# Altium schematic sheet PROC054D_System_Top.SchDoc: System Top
size 558 x 431 mm; Date: Not shown in title block; ApprovedBy: Not shown in title block; CheckedBy: Not shown in title block; Author: Not shown in title block; CompanyName: Not shown in title block; DrawnBy: a0271760; Engineer: Not shown in title block; Organization: Not shown in title block; Address1: Not shown in title block; Address2: Not shown in title block; Address3: Not shown in title block; Address4: Not shown in title block; DocumentNumber: 2; Revision: Use project parameter SCH_Rev; SheetNumber: 2; SheetTotal: 19; PageSetup: Record=PageOptions¦CenterHorizontal=True¦CenterVertical=True¦PrintScale=1.00¦XCorrection=1.00¦YCorrection=1.00¦PrintKind=0¦BorderSize=5000000¦LeftOffset=0¦BottomOffset=0¦Orientation=2¦PaperLength=1000¦PaperWidth=1000¦Scale=100¦PaperSource=15¦PrintQuality=600¦MediaType=1¦DitherType=10¦PaperKind=Letter¦PrintScaleMode=1
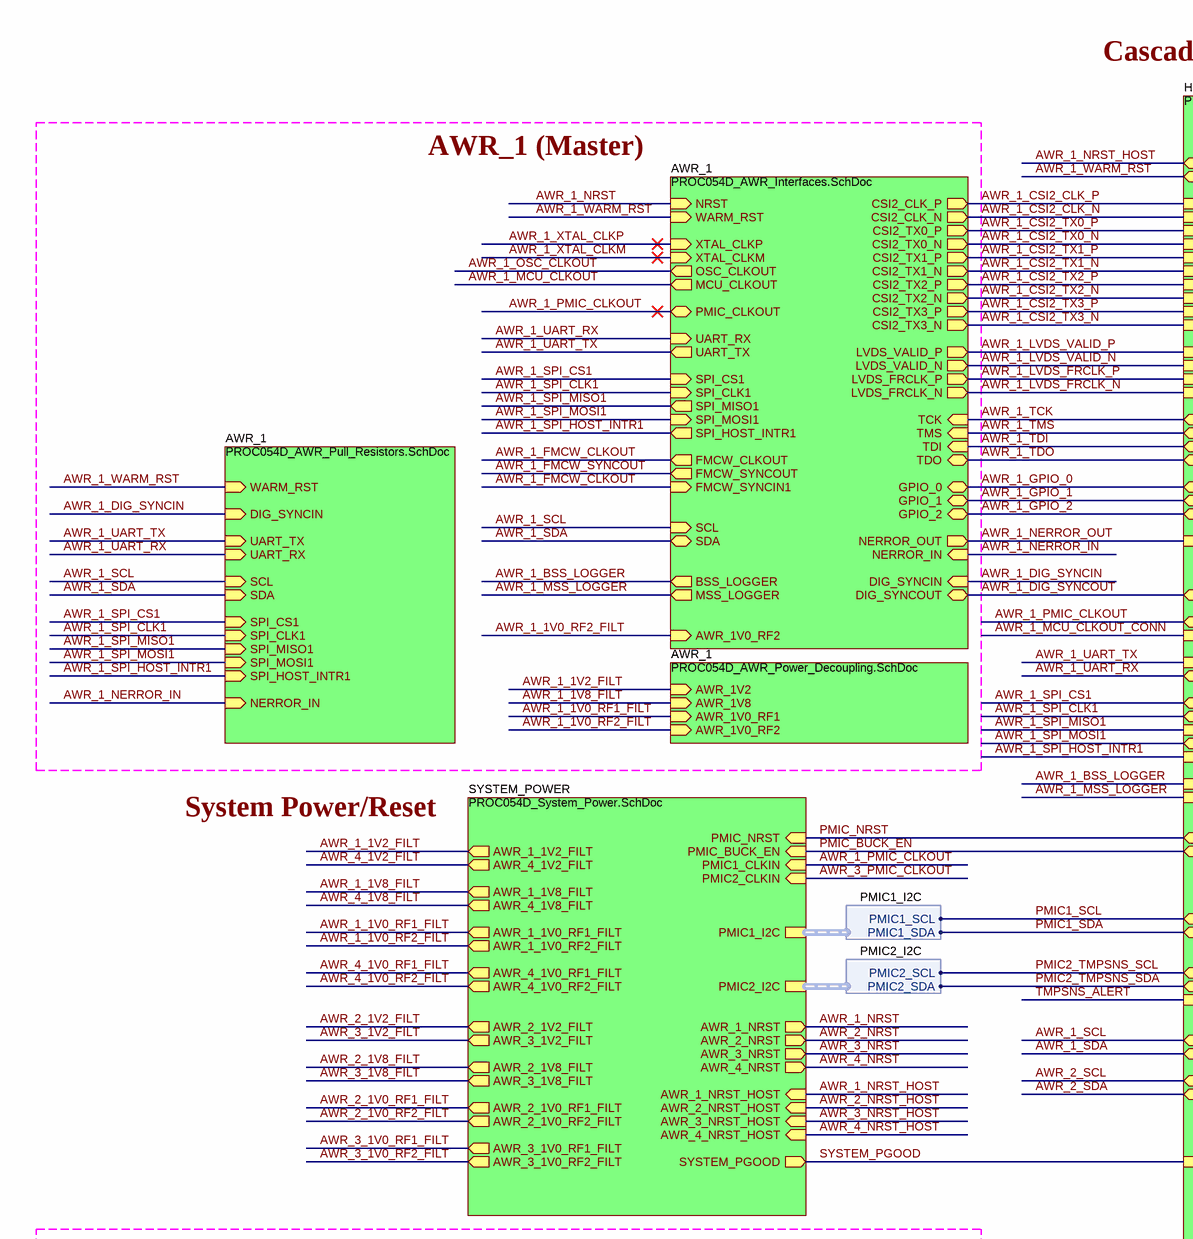
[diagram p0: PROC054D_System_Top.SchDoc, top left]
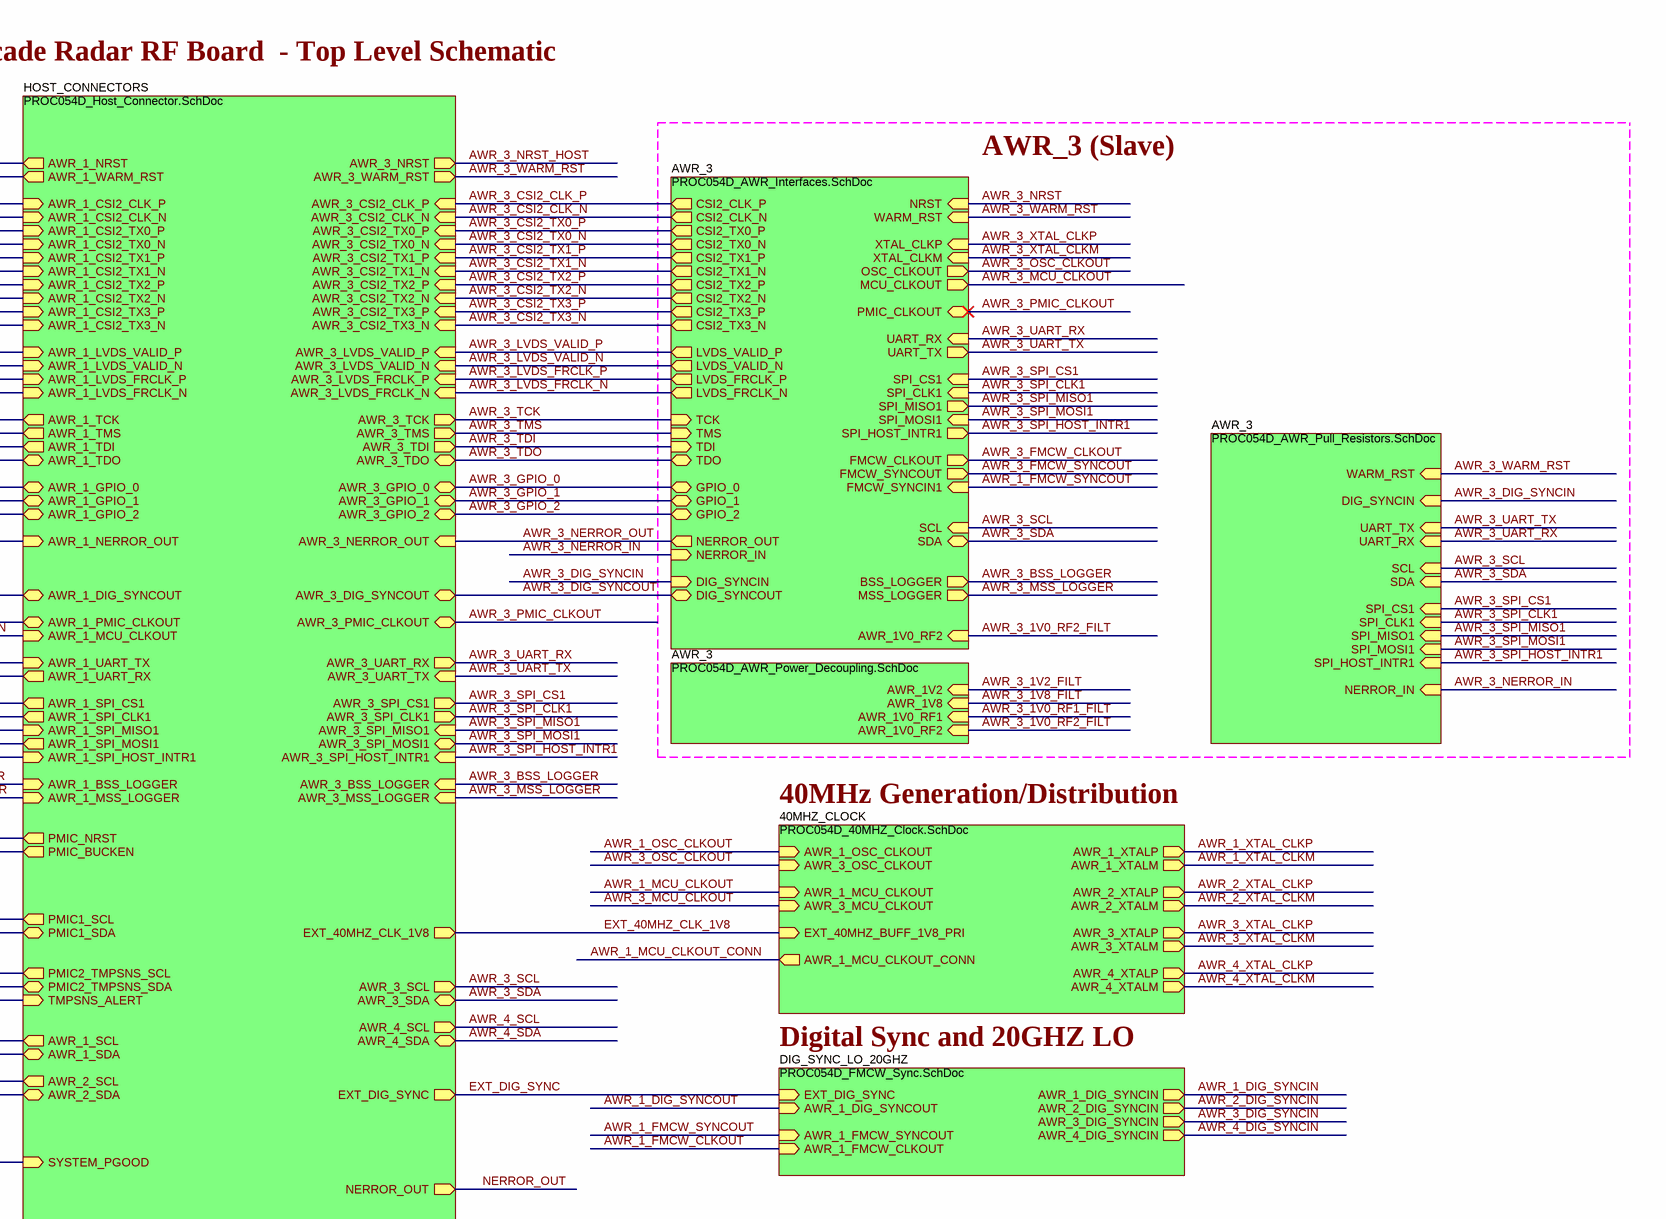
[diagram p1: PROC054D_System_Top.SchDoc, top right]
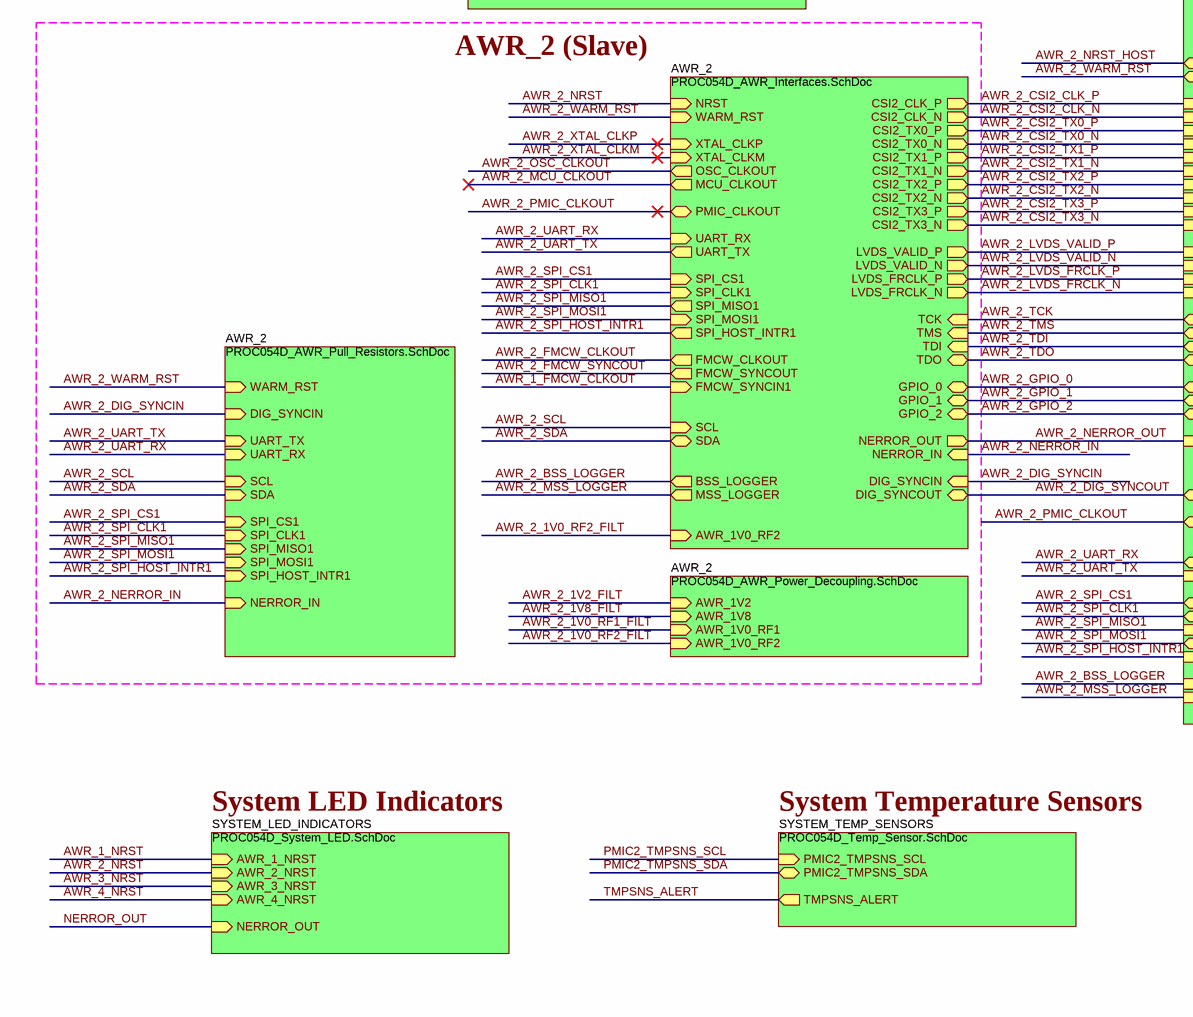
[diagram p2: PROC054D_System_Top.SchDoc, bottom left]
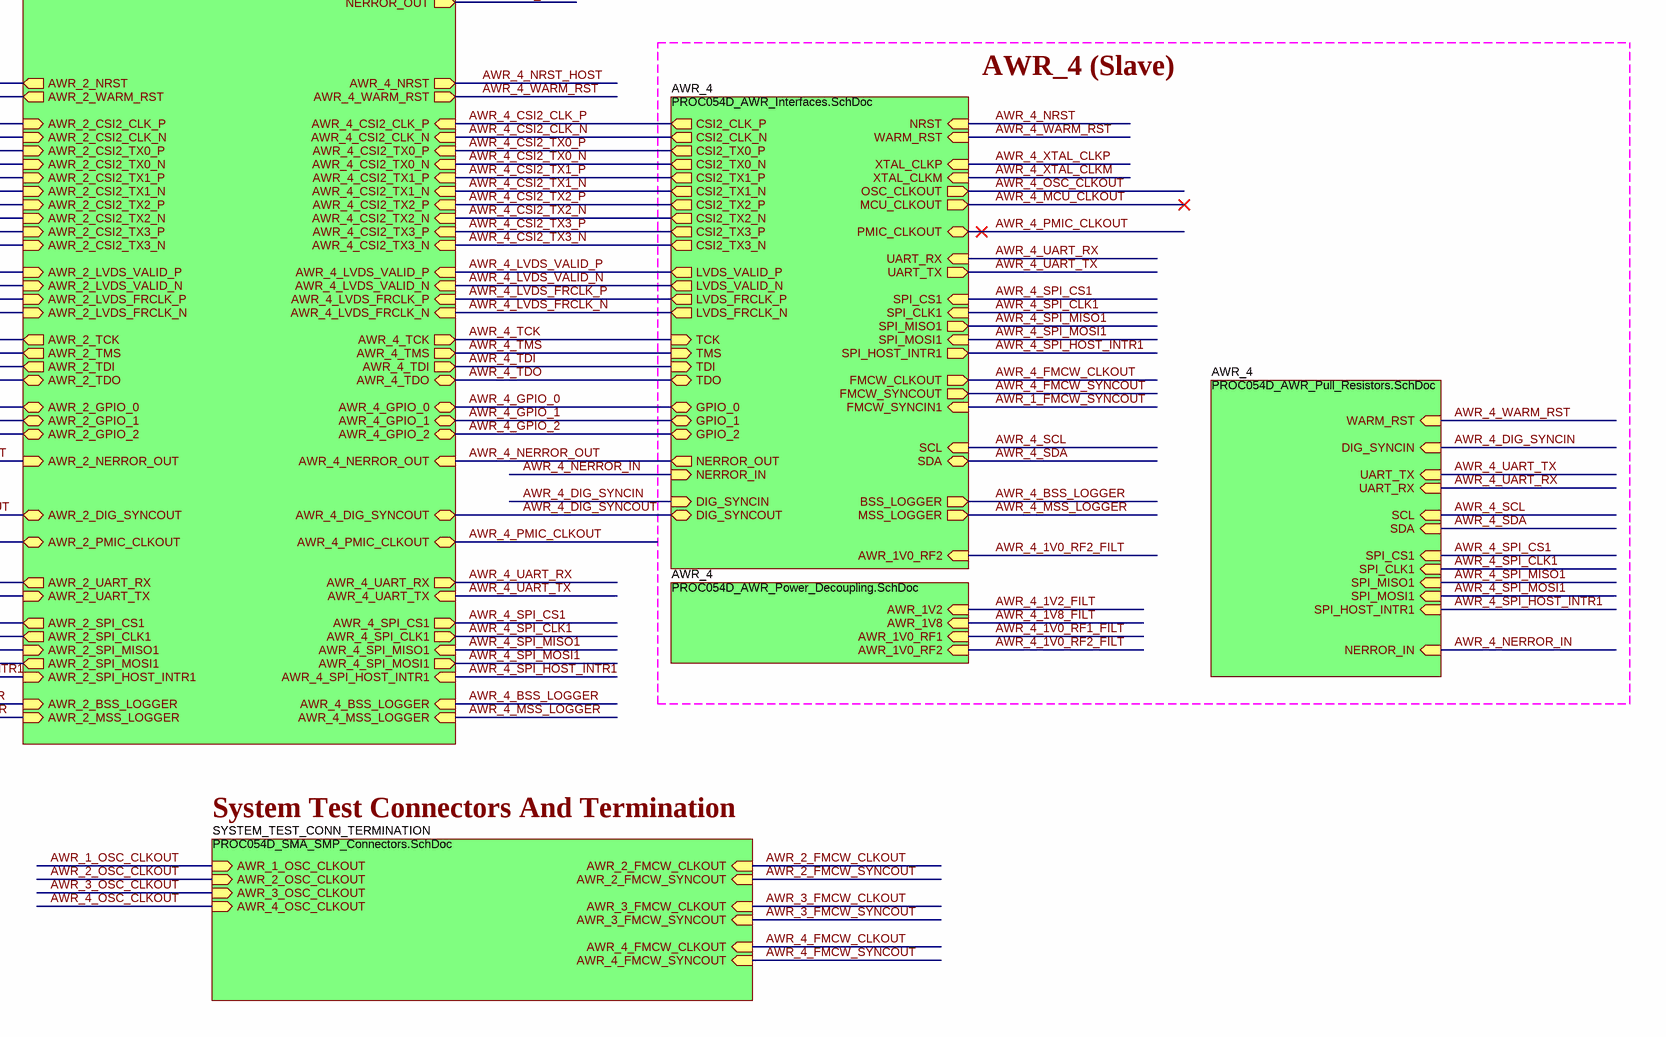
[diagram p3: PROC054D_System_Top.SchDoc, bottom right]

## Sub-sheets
40MHZ_CLOCK = PROC054D_40MHZ_Clock.SchDoc: AWR_4_XTALP (out), AWR_2_XTALP (out), AWR_3_XTALM (out), AWR_3_XTALP (out), AWR_4_XTALM (out), AWR_2_XTALM (out), AWR_1_XTALM (out), AWR_1_XTALP (out), EXT_40MHZ_BUFF_1V8_PRI (in), AWR_3_OSC_CLKOUT (in), AWR_1_MCU_CLKOUT (in), AWR_3_MCU_CLKOUT (in), AWR_1_OSC_CLKOUT (in), AWR_1_MCU_CLKOUT_CONN (out)
AWR_1 = PROC054D_AWR_Interfaces.SchDoc: OSC_CLKOUT (out), PMIC_CLKOUT (bidir), XTAL_CLKP (in), CSI2_TX2_P (out), CSI2_TX2_N (out), CSI2_TX3_P (out), CSI2_TX3_N (out), LVDS_FRCLK_P (out), LVDS_FRCLK_N (out), NERROR_OUT (out), NERROR_IN (in), XTAL_CLKM (in), LVDS_VALID_N (out), WARM_RST (in), NRST (in), CSI2_CLK_P (out), CSI2_CLK_N (out), TCK (in), CSI2_TX1_N (out), TDO (bidir), TMS (in), TDI (in), LVDS_VALID_P (out), CSI2_TX0_N (out), CSI2_TX1_P (out), CSI2_TX0_P (out), MCU_CLKOUT (out), DIG_SYNCOUT (bidir), DIG_SYNCIN (in), GPIO_0 (bidir), GPIO_1 (bidir), GPIO_2 (bidir), UART_RX (in), UART_TX (out), SPI_CLK1 (in), SPI_HOST_INTR1 (out), SPI_CS1 (in), SPI_MOSI1 (in), SPI_MISO1 (out), FMCW_SYNCIN1 (in), FMCW_CLKOUT (out), FMCW_SYNCOUT (out), SCL (in), SDA (bidir), BSS_LOGGER (out), MSS_LOGGER (out), AWR_1V0_RF2 (in)
AWR_1 = PROC054D_AWR_Power_Decoupling.SchDoc: AWR_1V0_RF1 (in), AWR_1V8 (in), AWR_1V2 (in), AWR_1V0_RF2 (in)
AWR_1 = PROC054D_AWR_Pull_Resistors.SchDoc: DIG_SYNCIN (in), SPI_CS1 (in), WARM_RST (in), UART_TX (in), UART_RX (in), SCL (in), SDA (in), SPI_CLK1 (in), SPI_MOSI1 (in), SPI_MISO1 (in), SPI_HOST_INTR1 (in), NERROR_IN (in)
AWR_2 = PROC054D_AWR_Interfaces.SchDoc: OSC_CLKOUT (out), PMIC_CLKOUT (bidir), XTAL_CLKP (in), CSI2_TX2_P (out), CSI2_TX2_N (out), CSI2_TX3_P (out), CSI2_TX3_N (out), LVDS_FRCLK_P (out), LVDS_FRCLK_N (out), NERROR_OUT (out), NERROR_IN (in), XTAL_CLKM (in), LVDS_VALID_N (out), WARM_RST (in), NRST (in), CSI2_CLK_P (out), CSI2_CLK_N (out), TCK (in), CSI2_TX1_N (out), TDO (bidir), TMS (in), TDI (in), LVDS_VALID_P (out), CSI2_TX0_N (out), CSI2_TX1_P (out), CSI2_TX0_P (out), MCU_CLKOUT (out), DIG_SYNCOUT (bidir), DIG_SYNCIN (in), GPIO_0 (bidir), GPIO_1 (bidir), GPIO_2 (bidir), UART_RX (in), UART_TX (out), SPI_CLK1 (in), SPI_HOST_INTR1 (out), SPI_CS1 (in), SPI_MOSI1 (in), SPI_MISO1 (out), FMCW_SYNCIN1 (in), FMCW_CLKOUT (out), FMCW_SYNCOUT (out), SCL (in), SDA (bidir), BSS_LOGGER (out), MSS_LOGGER (out), AWR_1V0_RF2 (in)
AWR_2 = PROC054D_AWR_Power_Decoupling.SchDoc: AWR_1V0_RF1 (in), AWR_1V8 (in), AWR_1V2 (in), AWR_1V0_RF2 (in)
AWR_2 = PROC054D_AWR_Pull_Resistors.SchDoc: DIG_SYNCIN (in), SPI_CS1 (in), WARM_RST (in), UART_TX (in), UART_RX (in), SCL (in), SDA (in), SPI_CLK1 (in), SPI_MOSI1 (in), SPI_MISO1 (in), SPI_HOST_INTR1 (in), NERROR_IN (in)
AWR_3 = PROC054D_AWR_Power_Decoupling.SchDoc: AWR_1V0_RF1 (in), AWR_1V8 (in), AWR_1V2 (in), AWR_1V0_RF2 (in)
AWR_3 = PROC054D_AWR_Pull_Resistors.SchDoc: DIG_SYNCIN (in), SPI_CS1 (in), WARM_RST (in), UART_TX (in), UART_RX (in), SCL (in), SDA (in), SPI_CLK1 (in), SPI_MOSI1 (in), SPI_MISO1 (in), SPI_HOST_INTR1 (in), NERROR_IN (in)
AWR_3 = PROC054D_AWR_Interfaces.SchDoc: OSC_CLKOUT (out), PMIC_CLKOUT (bidir), XTAL_CLKP (in), CSI2_TX2_P (out), CSI2_TX2_N (out), CSI2_TX3_P (out), CSI2_TX3_N (out), LVDS_FRCLK_P (out), LVDS_FRCLK_N (out), NERROR_OUT (out), NERROR_IN (in), XTAL_CLKM (in), LVDS_VALID_N (out), WARM_RST (in), NRST (in), CSI2_CLK_P (out), CSI2_CLK_N (out), TCK (in), CSI2_TX1_N (out), TDO (bidir), TMS (in), TDI (in), LVDS_VALID_P (out), CSI2_TX0_N (out), CSI2_TX1_P (out), CSI2_TX0_P (out), MCU_CLKOUT (out), DIG_SYNCOUT (bidir), DIG_SYNCIN (in), GPIO_0 (bidir), GPIO_1 (bidir), GPIO_2 (bidir), UART_RX (in), UART_TX (out), SPI_CLK1 (in), SPI_HOST_INTR1 (out), SPI_CS1 (in), SPI_MOSI1 (in), SPI_MISO1 (out), FMCW_SYNCIN1 (in), FMCW_CLKOUT (out), FMCW_SYNCOUT (out), SCL (in), SDA (bidir), BSS_LOGGER (out), MSS_LOGGER (out), AWR_1V0_RF2 (in)
AWR_4 = PROC054D_AWR_Interfaces.SchDoc: OSC_CLKOUT (out), PMIC_CLKOUT (bidir), XTAL_CLKP (in), CSI2_TX2_P (out), CSI2_TX2_N (out), CSI2_TX3_P (out), CSI2_TX3_N (out), LVDS_FRCLK_P (out), LVDS_FRCLK_N (out), NERROR_OUT (out), NERROR_IN (in), XTAL_CLKM (in), LVDS_VALID_N (out), WARM_RST (in), NRST (in), CSI2_CLK_P (out), CSI2_CLK_N (out), TCK (in), CSI2_TX1_N (out), TDO (bidir), TMS (in), TDI (in), LVDS_VALID_P (out), CSI2_TX0_N (out), CSI2_TX1_P (out), CSI2_TX0_P (out), MCU_CLKOUT (out), DIG_SYNCOUT (bidir), DIG_SYNCIN (in), GPIO_0 (bidir), GPIO_1 (bidir), GPIO_2 (bidir), UART_RX (in), UART_TX (out), SPI_CLK1 (in), SPI_HOST_INTR1 (out), SPI_CS1 (in), SPI_MOSI1 (in), SPI_MISO1 (out), FMCW_SYNCIN1 (in), FMCW_CLKOUT (out), FMCW_SYNCOUT (out), SCL (in), SDA (bidir), BSS_LOGGER (out), MSS_LOGGER (out), AWR_1V0_RF2 (in)
AWR_4 = PROC054D_AWR_Pull_Resistors.SchDoc: DIG_SYNCIN (in), SPI_CS1 (in), WARM_RST (in), UART_TX (in), UART_RX (in), SCL (in), SDA (in), SPI_CLK1 (in), SPI_MOSI1 (in), SPI_MISO1 (in), SPI_HOST_INTR1 (in), NERROR_IN (in)
AWR_4 = PROC054D_AWR_Power_Decoupling.SchDoc: AWR_1V0_RF1 (in), AWR_1V8 (in), AWR_1V2 (in), AWR_1V0_RF2 (in)
DIG_SYNC_LO_20GHZ = PROC054D_FMCW_Sync.SchDoc: AWR_2_DIG_SYNCIN (out), AWR_4_DIG_SYNCIN (out), EXT_DIG_SYNC (in), AWR_1_DIG_SYNCOUT (in), AWR_1_DIG_SYNCIN (out), AWR_3_DIG_SYNCIN (out), AWR_1_FMCW_SYNCOUT (in), AWR_1_FMCW_CLKOUT (in)
HOST_CONNECTORS = PROC054D_Host_Connector.SchDoc: AWR_1_GPIO_2 (bidir), AWR_1_GPIO_1 (bidir), AWR_1_GPIO_0 (bidir), AWR_1_CSI2_TX0_N (in), AWR_1_TDO (bidir), AWR_1_DIG_SYNCOUT (bidir), AWR_1_CSI2_CLK_N (in), AWR_1_CSI2_TX1_N (in), AWR_1_CSI2_TX0_P (in), AWR_1_CSI2_TX1_P (in), AWR_1_CSI2_TX2_N (in), AWR_1_CSI2_CLK_P (in), AWR_1_CSI2_TX2_P (in), AWR_1_CSI2_TX3_N (in), AWR_1_CSI2_TX3_P (in), AWR_1_LVDS_FRCLK_P (in), AWR_1_LVDS_FRCLK_N (in), AWR_1_LVDS_VALID_N (in), AWR_1_LVDS_VALID_P (in), AWR_1_MCU_CLKOUT (in), AWR_1_UART_RX (out), AWR_1_TMS (out), AWR_1_TDI (out), AWR_1_WARM_RST (out), AWR_1_TCK (out), AWR_1_NRST (out), AWR_1_UART_TX (in), AWR_1_NERROR_OUT (in), AWR_1_PMIC_CLKOUT (bidir), AWR_2_TDI (out), AWR_2_TMS (out), AWR_2_TCK (out), AWR_2_WARM_RST (out), AWR_2_NRST (out), AWR_2_GPIO_1 (bidir), AWR_2_GPIO_0 (bidir), AWR_2_BSS_LOGGER (in), AWR_2_MSS_LOGGER (in), AWR_2_GPIO_2 (bidir), AWR_2_UART_TX (in), AWR_2_UART_RX (out), AWR_2_SPI_CLK1 (out), AWR_2_SPI_MOSI1 (out), AWR_2_SPI_CS1 (out), AWR_2_SPI_HOST_INTR1 (in), AWR_2_NERROR_OUT (in), AWR_2_TDO (bidir), AWR_2_SPI_MISO1 (in), AWR_2_PMIC_CLKOUT (bidir), AWR_2_DIG_SYNCOUT (bidir), AWR_2_CSI2_TX3_P (in), AWR_2_CSI2_TX2_N (in), AWR_2_CSI2_TX0_P (in), AWR_2_CSI2_TX2_P (in), AWR_2_CSI2_TX3_N (in), AWR_2_CSI2_CLK_N (in), AWR_2_LVDS_FRCLK_N (in), AWR_2_CSI2_CLK_P (in), AWR_2_LVDS_FRCLK_P (in), AWR_2_LVDS_VALID_N (in), AWR_2_LVDS_VALID_P (in), AWR_2_CSI2_TX0_N (in), AWR_2_CSI2_TX1_P (in), AWR_2_CSI2_TX1_N (in), AWR_1_SPI_CLK1 (out), AWR_1_SPI_MOSI1 (out), AWR_1_SPI_CS1 (out), AWR_1_SPI_HOST_INTR1 (in), AWR_1_BSS_LOGGER (in), AWR_1_SPI_MISO1 (in), AWR_1_MSS_LOGGER (in), AWR_3_NRST (out), AWR_3_TCK (out), AWR_3_CSI2_TX3_P (in), AWR_3_LVDS_FRCLK_N (in), AWR_3_LVDS_FRCLK_P (in), AWR_3_GPIO_1 (bidir), AWR_3_WARM_RST (out), AWR_3_UART_RX (out), AWR_3_UART_TX (in), AWR_3_BSS_LOGGER (in), AWR_3_TMS (out), AWR_3_CSI2_TX1_P (in), AWR_3_CSI2_TX1_N (in), AWR_3_TDI (out), AWR_3_PMIC_CLKOUT (bidir), AWR_3_DIG_SYNCOUT (bidir), AWR_3_CSI2_TX2_N (in), AWR_3_CSI2_TX0_N (in), AWR_3_CSI2_TX0_P (in), AWR_3_CSI2_CLK_P (in), AWR_3_CSI2_CLK_N (in), AWR_3_GPIO_0 (bidir), AWR_3_GPIO_2 (bidir), AWR_3_CSI2_TX3_N (in), AWR_3_MSS_LOGGER (in), AWR_3_SPI_MISO1 (in), AWR_3_SPI_HOST_INTR1 (in), AWR_3_SPI_CS1 (out), AWR_3_SPI_MOSI1 (bidir), AWR_3_CSI2_TX2_P (in), AWR_3_LVDS_VALID_P (in), AWR_3_LVDS_VALID_N (in), AWR_3_TDO (bidir), AWR_3_NERROR_OUT (in), AWR_3_SPI_CLK1 (out), AWR_4_GPIO_2 (bidir), AWR_4_GPIO_0 (bidir), AWR_4_GPIO_1 (bidir), AWR_4_CSI2_CLK_N (in), AWR_4_CSI2_CLK_P (in), AWR_4_DIG_SYNCOUT (bidir), AWR_4_PMIC_CLKOUT (bidir), AWR_4_TDO (bidir), AWR_4_NERROR_OUT (in), AWR_4_CSI2_TX3_P (in), AWR_4_CSI2_TX3_N (in), AWR_4_CSI2_TX2_N (in), AWR_4_LVDS_FRCLK_N (in), AWR_4_CSI2_TX2_P (in), AWR_4_LVDS_FRCLK_P (in), AWR_4_LVDS_VALID_N (in), AWR_4_LVDS_VALID_P (in), AWR_4_SPI_MISO1 (in), AWR_4_CSI2_TX0_N (in), AWR_4_SPI_HOST_INTR1 (in), AWR_4_SPI_CS1 (out), AWR_4_SPI_CLK1 (out), AWR_4_SPI_MOSI1 (out), AWR_4_UART_RX (out), AWR_4_MSS_LOGGER (in), AWR_4_UART_TX (in), AWR_4_BSS_LOGGER (in), AWR_4_CSI2_TX0_P (in), AWR_4_CSI2_TX1_P (in), AWR_4_CSI2_TX1_N (in), AWR_4_NRST (out), AWR_4_TDI (out), AWR_4_TMS (out), AWR_4_WARM_RST (out), AWR_4_TCK (out), PMIC2_TMPSNS_SDA (bidir), PMIC_NRST (out), TMPSNS_ALERT (in), PMIC_BUCKEN (out), EXT_40MHZ_CLK_1V8 (out), PMIC2_TMPSNS_SCL (out), EXT_DIG_SYNC (out), PMIC1_SCL (out), PMIC1_SDA (bidir), SYSTEM_PGOOD (in), AWR_1_SCL (out), AWR_1_SDA (bidir), AWR_2_SCL (out), AWR_2_SDA (bidir), AWR_3_SCL (out), AWR_3_SDA (bidir), AWR_4_SCL (out), AWR_4_SDA (bidir), NERROR_OUT (out)
SYSTEM_LED_INDICATORS = PROC054D_System_LED.SchDoc: AWR_4_NRST (in), AWR_2_NRST (in), AWR_1_NRST (in), AWR_3_NRST (in), NERROR_OUT (in)
SYSTEM_POWER = PROC054D_System_Power.SchDoc: PMIC_BUCK_EN (in), PMIC_NRST (in), PMIC2_CLKIN (in), PMIC1_CLKIN (in), SYSTEM_PGOOD (out), AWR_1_NRST (out), AWR_2_NRST (out), AWR_3_NRST (out), AWR_4_NRST (out), PMIC1_I2C (harness PMIC1_I2C), PMIC2_I2C (harness PMIC2_I2C), AWR_4_NRST_HOST (in), AWR_3_NRST_HOST (in), AWR_1_NRST_HOST (in), AWR_2_NRST_HOST (in), AWR_1_1V2_FILT (out), AWR_4_1V2_FILT (out), AWR_1_1V8_FILT (out), AWR_4_1V8_FILT (out), AWR_4_1V0_RF2_FILT (out), AWR_1_1V0_RF1_FILT (out), AWR_1_1V0_RF2_FILT (out), AWR_4_1V0_RF1_FILT (out), AWR_2_1V2_FILT (out), AWR_3_1V2_FILT (out), AWR_2_1V8_FILT (out), AWR_3_1V8_FILT (out), AWR_2_1V0_RF1_FILT (out), AWR_3_1V0_RF1_FILT (out), AWR_2_1V0_RF2_FILT (out), AWR_3_1V0_RF2_FILT (out)
SYSTEM_TEMP_SENSORS = PROC054D_Temp_Sensor.SchDoc: PMIC2_TMPSNS_SDA (bidir), TMPSNS_ALERT (out), PMIC2_TMPSNS_SCL (in)
SYSTEM_TEST_CONN_TERMINATION = PROC054D_SMA_SMP_Connectors.SchDoc: AWR_1_OSC_CLKOUT (in), AWR_3_OSC_CLKOUT (in), AWR_4_OSC_CLKOUT (in), AWR_2_OSC_CLKOUT (in), AWR_3_FMCW_CLKOUT (in), AWR_2_FMCW_CLKOUT (in), AWR_4_FMCW_CLKOUT (in), AWR_2_FMCW_SYNCOUT (in), AWR_3_FMCW_SYNCOUT (in), AWR_4_FMCW_SYNCOUT (in)

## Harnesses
PMIC1_I2C: PMIC1_SCL, PMIC1_SDA
PMIC2_I2C: PMIC2_SCL, PMIC2_SDA

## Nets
AWR_1_1V0_RF1_FILT: sheet AWR_1/AWR_1V0_RF1, sheet SYSTEM_POWER/AWR_1_1V0_RF1_FILT
AWR_1_1V0_RF2_FILT: sheet AWR_1/AWR_1V0_RF2, sheet AWR_1/AWR_1V0_RF2, sheet SYSTEM_POWER/AWR_1_1V0_RF2_FILT
AWR_1_1V2_FILT: sheet AWR_1/AWR_1V2, sheet SYSTEM_POWER/AWR_1_1V2_FILT
AWR_1_1V8_FILT: sheet AWR_1/AWR_1V8, sheet SYSTEM_POWER/AWR_1_1V8_FILT
AWR_1_BSS_LOGGER: sheet AWR_1/BSS_LOGGER, sheet HOST_CONNECTORS/AWR_1_BSS_LOGGER
AWR_1_CSI2_CLK_N: sheet AWR_1/CSI2_CLK_N, sheet HOST_CONNECTORS/AWR_1_CSI2_CLK_N
AWR_1_CSI2_CLK_P: sheet AWR_1/CSI2_CLK_P, sheet HOST_CONNECTORS/AWR_1_CSI2_CLK_P
AWR_1_CSI2_TX0_N: sheet AWR_1/CSI2_TX0_N, sheet HOST_CONNECTORS/AWR_1_CSI2_TX0_N
AWR_1_CSI2_TX0_P: sheet AWR_1/CSI2_TX0_P, sheet HOST_CONNECTORS/AWR_1_CSI2_TX0_P
AWR_1_CSI2_TX1_N: sheet AWR_1/CSI2_TX1_N, sheet HOST_CONNECTORS/AWR_1_CSI2_TX1_N
AWR_1_CSI2_TX1_P: sheet AWR_1/CSI2_TX1_P, sheet HOST_CONNECTORS/AWR_1_CSI2_TX1_P
AWR_1_CSI2_TX2_N: sheet AWR_1/CSI2_TX2_N, sheet HOST_CONNECTORS/AWR_1_CSI2_TX2_N
AWR_1_CSI2_TX2_P: sheet AWR_1/CSI2_TX2_P, sheet HOST_CONNECTORS/AWR_1_CSI2_TX2_P
AWR_1_CSI2_TX3_N: sheet AWR_1/CSI2_TX3_N, sheet HOST_CONNECTORS/AWR_1_CSI2_TX3_N
AWR_1_CSI2_TX3_P: sheet AWR_1/CSI2_TX3_P, sheet HOST_CONNECTORS/AWR_1_CSI2_TX3_P
AWR_1_DIG_SYNCIN: sheet DIG_SYNC_LO_20GHZ/AWR_1_DIG_SYNCIN, sheet AWR_1/DIG_SYNCIN, sheet AWR_1/DIG_SYNCIN
AWR_1_DIG_SYNCOUT: sheet DIG_SYNC_LO_20GHZ/AWR_1_DIG_SYNCOUT, sheet AWR_1/DIG_SYNCOUT, sheet HOST_CONNECTORS/AWR_1_DIG_SYNCOUT
AWR_1_FMCW_CLKOUT: sheet DIG_SYNC_LO_20GHZ/AWR_1_FMCW_CLKOUT, sheet AWR_1/FMCW_SYNCIN1, sheet AWR_1/FMCW_CLKOUT, sheet AWR_2/FMCW_SYNCIN1
AWR_1_FMCW_SYNCOUT: sheet DIG_SYNC_LO_20GHZ/AWR_1_FMCW_SYNCOUT, sheet AWR_1/FMCW_SYNCOUT, sheet AWR_3/FMCW_SYNCIN1, sheet AWR_4/FMCW_SYNCIN1
AWR_1_GPIO_0: sheet AWR_1/GPIO_0, sheet HOST_CONNECTORS/AWR_1_GPIO_0
AWR_1_GPIO_1: sheet AWR_1/GPIO_1, sheet HOST_CONNECTORS/AWR_1_GPIO_1
AWR_1_GPIO_2: sheet AWR_1/GPIO_2, sheet HOST_CONNECTORS/AWR_1_GPIO_2
AWR_1_LVDS_FRCLK_N: sheet AWR_1/LVDS_FRCLK_N, sheet HOST_CONNECTORS/AWR_1_LVDS_FRCLK_N
AWR_1_LVDS_FRCLK_P: sheet AWR_1/LVDS_FRCLK_P, sheet HOST_CONNECTORS/AWR_1_LVDS_FRCLK_P
AWR_1_LVDS_VALID_N: sheet AWR_1/LVDS_VALID_N, sheet HOST_CONNECTORS/AWR_1_LVDS_VALID_N
AWR_1_LVDS_VALID_P: sheet AWR_1/LVDS_VALID_P, sheet HOST_CONNECTORS/AWR_1_LVDS_VALID_P
AWR_1_MCU_CLKOUT: sheet 40MHZ_CLOCK/AWR_1_MCU_CLKOUT, sheet AWR_1/MCU_CLKOUT
AWR_1_MCU_CLKOUT_CONN: sheet 40MHZ_CLOCK/AWR_1_MCU_CLKOUT_CONN, sheet HOST_CONNECTORS/AWR_1_MCU_CLKOUT
AWR_1_MSS_LOGGER: sheet AWR_1/MSS_LOGGER, sheet HOST_CONNECTORS/AWR_1_MSS_LOGGER
AWR_1_NERROR_IN: sheet AWR_1/NERROR_IN, sheet AWR_1/NERROR_IN
AWR_1_NERROR_OUT: sheet AWR_1/NERROR_OUT, sheet HOST_CONNECTORS/AWR_1_NERROR_OUT
AWR_1_NRST: sheet AWR_1/NRST, sheet SYSTEM_POWER/AWR_1_NRST, sheet SYSTEM_LED_INDICATORS/AWR_1_NRST
AWR_1_NRST_HOST: sheet SYSTEM_POWER/AWR_1_NRST_HOST, sheet HOST_CONNECTORS/AWR_1_NRST
AWR_1_OSC_CLKOUT: sheet 40MHZ_CLOCK/AWR_1_OSC_CLKOUT, sheet SYSTEM_TEST_CONN_TERMINATION/AWR_1_OSC_CLKOUT, sheet AWR_1/OSC_CLKOUT
AWR_1_PMIC_CLKOUT: sheet AWR_1/PMIC_CLKOUT, sheet SYSTEM_POWER/PMIC1_CLKIN, sheet HOST_CONNECTORS/AWR_1_PMIC_CLKOUT
AWR_1_SCL: sheet AWR_1/SCL, sheet AWR_1/SCL, sheet HOST_CONNECTORS/AWR_1_SCL
AWR_1_SDA: sheet AWR_1/SDA, sheet AWR_1/SDA, sheet HOST_CONNECTORS/AWR_1_SDA
AWR_1_SPI_CLK1: sheet AWR_1/SPI_CLK1, sheet AWR_1/SPI_CLK1, sheet HOST_CONNECTORS/AWR_1_SPI_CLK1
AWR_1_SPI_CS1: sheet AWR_1/SPI_CS1, sheet AWR_1/SPI_CS1, sheet HOST_CONNECTORS/AWR_1_SPI_CS1
AWR_1_SPI_HOST_INTR1: sheet AWR_1/SPI_HOST_INTR1, sheet AWR_1/SPI_HOST_INTR1, sheet HOST_CONNECTORS/AWR_1_SPI_HOST_INTR1
AWR_1_SPI_MISO1: sheet AWR_1/SPI_MISO1, sheet AWR_1/SPI_MISO1, sheet HOST_CONNECTORS/AWR_1_SPI_MISO1
AWR_1_SPI_MOSI1: sheet AWR_1/SPI_MOSI1, sheet AWR_1/SPI_MOSI1, sheet HOST_CONNECTORS/AWR_1_SPI_MOSI1
AWR_1_TCK: sheet AWR_1/TCK, sheet HOST_CONNECTORS/AWR_1_TCK
AWR_1_TDI: sheet AWR_1/TDI, sheet HOST_CONNECTORS/AWR_1_TDI
AWR_1_TDO: sheet AWR_1/TDO, sheet HOST_CONNECTORS/AWR_1_TDO
AWR_1_TMS: sheet AWR_1/TMS, sheet HOST_CONNECTORS/AWR_1_TMS
AWR_1_UART_RX: sheet AWR_1/UART_RX, sheet AWR_1/UART_RX, sheet HOST_CONNECTORS/AWR_1_UART_RX
AWR_1_UART_TX: sheet AWR_1/UART_TX, sheet AWR_1/UART_TX, sheet HOST_CONNECTORS/AWR_1_UART_TX
AWR_1_WARM_RST: sheet AWR_1/WARM_RST, sheet AWR_1/WARM_RST, sheet HOST_CONNECTORS/AWR_1_WARM_RST
AWR_1_XTAL_CLKM: sheet 40MHZ_CLOCK/AWR_1_XTALM, sheet AWR_1/XTAL_CLKM
AWR_1_XTAL_CLKP: sheet 40MHZ_CLOCK/AWR_1_XTALP, sheet AWR_1/XTAL_CLKP
AWR_2_1V0_RF1_FILT: sheet SYSTEM_POWER/AWR_2_1V0_RF1_FILT, sheet AWR_2/AWR_1V0_RF1
AWR_2_1V0_RF2_FILT: sheet SYSTEM_POWER/AWR_2_1V0_RF2_FILT, sheet AWR_2/AWR_1V0_RF2, sheet AWR_2/AWR_1V0_RF2
AWR_2_1V2_FILT: sheet SYSTEM_POWER/AWR_2_1V2_FILT, sheet AWR_2/AWR_1V2
AWR_2_1V8_FILT: sheet SYSTEM_POWER/AWR_2_1V8_FILT, sheet AWR_2/AWR_1V8
AWR_2_BSS_LOGGER: sheet HOST_CONNECTORS/AWR_2_BSS_LOGGER, sheet AWR_2/BSS_LOGGER
AWR_2_CSI2_CLK_N: sheet HOST_CONNECTORS/AWR_2_CSI2_CLK_N, sheet AWR_2/CSI2_CLK_N
AWR_2_CSI2_CLK_P: sheet HOST_CONNECTORS/AWR_2_CSI2_CLK_P, sheet AWR_2/CSI2_CLK_P
AWR_2_CSI2_TX0_N: sheet HOST_CONNECTORS/AWR_2_CSI2_TX0_N, sheet AWR_2/CSI2_TX0_N
AWR_2_CSI2_TX0_P: sheet HOST_CONNECTORS/AWR_2_CSI2_TX0_P, sheet AWR_2/CSI2_TX0_P
AWR_2_CSI2_TX1_N: sheet HOST_CONNECTORS/AWR_2_CSI2_TX1_N, sheet AWR_2/CSI2_TX1_N
AWR_2_CSI2_TX1_P: sheet HOST_CONNECTORS/AWR_2_CSI2_TX1_P, sheet AWR_2/CSI2_TX1_P
AWR_2_CSI2_TX2_N: sheet HOST_CONNECTORS/AWR_2_CSI2_TX2_N, sheet AWR_2/CSI2_TX2_N
AWR_2_CSI2_TX2_P: sheet HOST_CONNECTORS/AWR_2_CSI2_TX2_P, sheet AWR_2/CSI2_TX2_P
AWR_2_CSI2_TX3_N: sheet HOST_CONNECTORS/AWR_2_CSI2_TX3_N, sheet AWR_2/CSI2_TX3_N
AWR_2_CSI2_TX3_P: sheet HOST_CONNECTORS/AWR_2_CSI2_TX3_P, sheet AWR_2/CSI2_TX3_P
AWR_2_DIG_SYNCIN: sheet DIG_SYNC_LO_20GHZ/AWR_2_DIG_SYNCIN, sheet AWR_2/DIG_SYNCIN, sheet AWR_2/DIG_SYNCIN
AWR_2_DIG_SYNCOUT: sheet HOST_CONNECTORS/AWR_2_DIG_SYNCOUT, sheet AWR_2/DIG_SYNCOUT
AWR_2_FMCW_CLKOUT: sheet SYSTEM_TEST_CONN_TERMINATION/AWR_2_FMCW_CLKOUT, sheet AWR_2/FMCW_CLKOUT
AWR_2_FMCW_SYNCOUT: sheet SYSTEM_TEST_CONN_TERMINATION/AWR_2_FMCW_SYNCOUT, sheet AWR_2/FMCW_SYNCOUT
AWR_2_GPIO_0: sheet HOST_CONNECTORS/AWR_2_GPIO_0, sheet AWR_2/GPIO_0
AWR_2_GPIO_1: sheet HOST_CONNECTORS/AWR_2_GPIO_1, sheet AWR_2/GPIO_1
AWR_2_GPIO_2: sheet HOST_CONNECTORS/AWR_2_GPIO_2, sheet AWR_2/GPIO_2
AWR_2_LVDS_FRCLK_N: sheet HOST_CONNECTORS/AWR_2_LVDS_FRCLK_N, sheet AWR_2/LVDS_FRCLK_N
AWR_2_LVDS_FRCLK_P: sheet HOST_CONNECTORS/AWR_2_LVDS_FRCLK_P, sheet AWR_2/LVDS_FRCLK_P
AWR_2_LVDS_VALID_N: sheet HOST_CONNECTORS/AWR_2_LVDS_VALID_N, sheet AWR_2/LVDS_VALID_N
AWR_2_LVDS_VALID_P: sheet HOST_CONNECTORS/AWR_2_LVDS_VALID_P, sheet AWR_2/LVDS_VALID_P
AWR_2_MSS_LOGGER: sheet HOST_CONNECTORS/AWR_2_MSS_LOGGER, sheet AWR_2/MSS_LOGGER
AWR_2_NERROR_IN: sheet AWR_2/NERROR_IN, sheet AWR_2/NERROR_IN
AWR_2_NERROR_OUT: sheet HOST_CONNECTORS/AWR_2_NERROR_OUT, sheet AWR_2/NERROR_OUT
AWR_2_NRST: sheet SYSTEM_POWER/AWR_2_NRST, sheet SYSTEM_LED_INDICATORS/AWR_2_NRST, sheet AWR_2/NRST
AWR_2_NRST_HOST: sheet SYSTEM_POWER/AWR_2_NRST_HOST, sheet HOST_CONNECTORS/AWR_2_NRST
AWR_2_OSC_CLKOUT: sheet SYSTEM_TEST_CONN_TERMINATION/AWR_2_OSC_CLKOUT, sheet AWR_2/OSC_CLKOUT
AWR_2_PMIC_CLKOUT: sheet HOST_CONNECTORS/AWR_2_PMIC_CLKOUT, sheet AWR_2/PMIC_CLKOUT
AWR_2_SCL: sheet HOST_CONNECTORS/AWR_2_SCL, sheet AWR_2/SCL, sheet AWR_2/SCL
AWR_2_SDA: sheet HOST_CONNECTORS/AWR_2_SDA, sheet AWR_2/SDA, sheet AWR_2/SDA
AWR_2_SPI_CLK1: sheet HOST_CONNECTORS/AWR_2_SPI_CLK1, sheet AWR_2/SPI_CLK1, sheet AWR_2/SPI_CLK1
AWR_2_SPI_CS1: sheet HOST_CONNECTORS/AWR_2_SPI_CS1, sheet AWR_2/SPI_CS1, sheet AWR_2/SPI_CS1
AWR_2_SPI_HOST_INTR1: sheet HOST_CONNECTORS/AWR_2_SPI_HOST_INTR1, sheet AWR_2/SPI_HOST_INTR1, sheet AWR_2/SPI_HOST_INTR1
AWR_2_SPI_MISO1: sheet HOST_CONNECTORS/AWR_2_SPI_MISO1, sheet AWR_2/SPI_MISO1, sheet AWR_2/SPI_MISO1
AWR_2_SPI_MOSI1: sheet HOST_CONNECTORS/AWR_2_SPI_MOSI1, sheet AWR_2/SPI_MOSI1, sheet AWR_2/SPI_MOSI1
AWR_2_TCK: sheet HOST_CONNECTORS/AWR_2_TCK, sheet AWR_2/TCK
AWR_2_TDI: sheet HOST_CONNECTORS/AWR_2_TDI, sheet AWR_2/TDI
AWR_2_TDO: sheet HOST_CONNECTORS/AWR_2_TDO, sheet AWR_2/TDO
AWR_2_TMS: sheet HOST_CONNECTORS/AWR_2_TMS, sheet AWR_2/TMS
AWR_2_UART_RX: sheet HOST_CONNECTORS/AWR_2_UART_RX, sheet AWR_2/UART_RX, sheet AWR_2/UART_RX
AWR_2_UART_TX: sheet HOST_CONNECTORS/AWR_2_UART_TX, sheet AWR_2/UART_TX, sheet AWR_2/UART_TX
AWR_2_WARM_RST: sheet HOST_CONNECTORS/AWR_2_WARM_RST, sheet AWR_2/WARM_RST, sheet AWR_2/WARM_RST
AWR_2_XTAL_CLKM: sheet 40MHZ_CLOCK/AWR_2_XTALM, sheet AWR_2/XTAL_CLKM
AWR_2_XTAL_CLKP: sheet 40MHZ_CLOCK/AWR_2_XTALP, sheet AWR_2/XTAL_CLKP
AWR_3_1V0_RF1_FILT: sheet SYSTEM_POWER/AWR_3_1V0_RF1_FILT, sheet AWR_3/AWR_1V0_RF1
AWR_3_1V0_RF2_FILT: sheet SYSTEM_POWER/AWR_3_1V0_RF2_FILT, sheet AWR_3/AWR_1V0_RF2, sheet AWR_3/AWR_1V0_RF2
AWR_3_1V2_FILT: sheet SYSTEM_POWER/AWR_3_1V2_FILT, sheet AWR_3/AWR_1V2
AWR_3_1V8_FILT: sheet SYSTEM_POWER/AWR_3_1V8_FILT, sheet AWR_3/AWR_1V8
AWR_3_BSS_LOGGER: sheet HOST_CONNECTORS/AWR_3_BSS_LOGGER, sheet AWR_3/BSS_LOGGER
AWR_3_CSI2_CLK_N: sheet HOST_CONNECTORS/AWR_3_CSI2_CLK_N, sheet AWR_3/CSI2_CLK_N
AWR_3_CSI2_CLK_P: sheet HOST_CONNECTORS/AWR_3_CSI2_CLK_P, sheet AWR_3/CSI2_CLK_P
AWR_3_CSI2_TX0_N: sheet HOST_CONNECTORS/AWR_3_CSI2_TX0_N, sheet AWR_3/CSI2_TX0_N
AWR_3_CSI2_TX0_P: sheet HOST_CONNECTORS/AWR_3_CSI2_TX0_P, sheet AWR_3/CSI2_TX0_P
AWR_3_CSI2_TX1_N: sheet HOST_CONNECTORS/AWR_3_CSI2_TX1_N, sheet AWR_3/CSI2_TX1_N
AWR_3_CSI2_TX1_P: sheet HOST_CONNECTORS/AWR_3_CSI2_TX1_P, sheet AWR_3/CSI2_TX1_P
AWR_3_CSI2_TX2_N: sheet HOST_CONNECTORS/AWR_3_CSI2_TX2_N, sheet AWR_3/CSI2_TX2_N
AWR_3_CSI2_TX2_P: sheet HOST_CONNECTORS/AWR_3_CSI2_TX2_P, sheet AWR_3/CSI2_TX2_P
AWR_3_CSI2_TX3_N: sheet HOST_CONNECTORS/AWR_3_CSI2_TX3_N, sheet AWR_3/CSI2_TX3_N
AWR_3_CSI2_TX3_P: sheet HOST_CONNECTORS/AWR_3_CSI2_TX3_P, sheet AWR_3/CSI2_TX3_P
AWR_3_DIG_SYNCIN: sheet DIG_SYNC_LO_20GHZ/AWR_3_DIG_SYNCIN, sheet AWR_3/DIG_SYNCIN, sheet AWR_3/DIG_SYNCIN
AWR_3_DIG_SYNCOUT: sheet HOST_CONNECTORS/AWR_3_DIG_SYNCOUT, sheet AWR_3/DIG_SYNCOUT
AWR_3_FMCW_CLKOUT: sheet SYSTEM_TEST_CONN_TERMINATION/AWR_3_FMCW_CLKOUT, sheet AWR_3/FMCW_CLKOUT
AWR_3_FMCW_SYNCOUT: sheet SYSTEM_TEST_CONN_TERMINATION/AWR_3_FMCW_SYNCOUT, sheet AWR_3/FMCW_SYNCOUT
AWR_3_GPIO_0: sheet HOST_CONNECTORS/AWR_3_GPIO_0, sheet AWR_3/GPIO_0
AWR_3_GPIO_1: sheet HOST_CONNECTORS/AWR_3_GPIO_1, sheet AWR_3/GPIO_1
AWR_3_GPIO_2: sheet HOST_CONNECTORS/AWR_3_GPIO_2, sheet AWR_3/GPIO_2
AWR_3_LVDS_FRCLK_N: sheet HOST_CONNECTORS/AWR_3_LVDS_FRCLK_N, sheet AWR_3/LVDS_FRCLK_N
AWR_3_LVDS_FRCLK_P: sheet HOST_CONNECTORS/AWR_3_LVDS_FRCLK_P, sheet AWR_3/LVDS_FRCLK_P
AWR_3_LVDS_VALID_N: sheet HOST_CONNECTORS/AWR_3_LVDS_VALID_N, sheet AWR_3/LVDS_VALID_N
AWR_3_LVDS_VALID_P: sheet HOST_CONNECTORS/AWR_3_LVDS_VALID_P, sheet AWR_3/LVDS_VALID_P
AWR_3_MCU_CLKOUT: sheet 40MHZ_CLOCK/AWR_3_MCU_CLKOUT, sheet AWR_3/MCU_CLKOUT
AWR_3_MSS_LOGGER: sheet HOST_CONNECTORS/AWR_3_MSS_LOGGER, sheet AWR_3/MSS_LOGGER
AWR_3_NERROR_IN: sheet AWR_3/NERROR_IN, sheet AWR_3/NERROR_IN
AWR_3_NERROR_OUT: sheet HOST_CONNECTORS/AWR_3_NERROR_OUT, sheet AWR_3/NERROR_OUT
AWR_3_NRST: sheet SYSTEM_POWER/AWR_3_NRST, sheet SYSTEM_LED_INDICATORS/AWR_3_NRST, sheet AWR_3/NRST
AWR_3_NRST_HOST: sheet SYSTEM_POWER/AWR_3_NRST_HOST, sheet HOST_CONNECTORS/AWR_3_NRST
AWR_3_OSC_CLKOUT: sheet 40MHZ_CLOCK/AWR_3_OSC_CLKOUT, sheet SYSTEM_TEST_CONN_TERMINATION/AWR_3_OSC_CLKOUT, sheet AWR_3/OSC_CLKOUT
AWR_3_PMIC_CLKOUT: sheet SYSTEM_POWER/PMIC2_CLKIN, sheet HOST_CONNECTORS/AWR_3_PMIC_CLKOUT, sheet AWR_3/PMIC_CLKOUT
AWR_3_SCL: sheet HOST_CONNECTORS/AWR_3_SCL, sheet AWR_3/SCL, sheet AWR_3/SCL
AWR_3_SDA: sheet HOST_CONNECTORS/AWR_3_SDA, sheet AWR_3/SDA, sheet AWR_3/SDA
AWR_3_SPI_CLK1: sheet HOST_CONNECTORS/AWR_3_SPI_CLK1, sheet AWR_3/SPI_CLK1, sheet AWR_3/SPI_CLK1
AWR_3_SPI_CS1: sheet HOST_CONNECTORS/AWR_3_SPI_CS1, sheet AWR_3/SPI_CS1, sheet AWR_3/SPI_CS1
AWR_3_SPI_HOST_INTR1: sheet HOST_CONNECTORS/AWR_3_SPI_HOST_INTR1, sheet AWR_3/SPI_HOST_INTR1, sheet AWR_3/SPI_HOST_INTR1
AWR_3_SPI_MISO1: sheet HOST_CONNECTORS/AWR_3_SPI_MISO1, sheet AWR_3/SPI_MISO1, sheet AWR_3/SPI_MISO1
AWR_3_SPI_MOSI1: sheet HOST_CONNECTORS/AWR_3_SPI_MOSI1, sheet AWR_3/SPI_MOSI1, sheet AWR_3/SPI_MOSI1
AWR_3_TCK: sheet HOST_CONNECTORS/AWR_3_TCK, sheet AWR_3/TCK
AWR_3_TDI: sheet HOST_CONNECTORS/AWR_3_TDI, sheet AWR_3/TDI
AWR_3_TDO: sheet HOST_CONNECTORS/AWR_3_TDO, sheet AWR_3/TDO
AWR_3_TMS: sheet HOST_CONNECTORS/AWR_3_TMS, sheet AWR_3/TMS
AWR_3_UART_RX: sheet HOST_CONNECTORS/AWR_3_UART_RX, sheet AWR_3/UART_RX, sheet AWR_3/UART_RX
AWR_3_UART_TX: sheet HOST_CONNECTORS/AWR_3_UART_TX, sheet AWR_3/UART_TX, sheet AWR_3/UART_TX
AWR_3_WARM_RST: sheet HOST_CONNECTORS/AWR_3_WARM_RST, sheet AWR_3/WARM_RST, sheet AWR_3/WARM_RST
AWR_3_XTAL_CLKM: sheet 40MHZ_CLOCK/AWR_3_XTALM, sheet AWR_3/XTAL_CLKM
AWR_3_XTAL_CLKP: sheet 40MHZ_CLOCK/AWR_3_XTALP, sheet AWR_3/XTAL_CLKP
AWR_4_1V0_RF1_FILT: sheet SYSTEM_POWER/AWR_4_1V0_RF1_FILT, sheet AWR_4/AWR_1V0_RF1
AWR_4_1V0_RF2_FILT: sheet SYSTEM_POWER/AWR_4_1V0_RF2_FILT, sheet AWR_4/AWR_1V0_RF2, sheet AWR_4/AWR_1V0_RF2
AWR_4_1V2_FILT: sheet SYSTEM_POWER/AWR_4_1V2_FILT, sheet AWR_4/AWR_1V2
AWR_4_1V8_FILT: sheet SYSTEM_POWER/AWR_4_1V8_FILT, sheet AWR_4/AWR_1V8
AWR_4_BSS_LOGGER: sheet HOST_CONNECTORS/AWR_4_BSS_LOGGER, sheet AWR_4/BSS_LOGGER
AWR_4_CSI2_CLK_N: sheet HOST_CONNECTORS/AWR_4_CSI2_CLK_N, sheet AWR_4/CSI2_CLK_N
AWR_4_CSI2_CLK_P: sheet HOST_CONNECTORS/AWR_4_CSI2_CLK_P, sheet AWR_4/CSI2_CLK_P
AWR_4_CSI2_TX0_N: sheet HOST_CONNECTORS/AWR_4_CSI2_TX0_N, sheet AWR_4/CSI2_TX0_N
AWR_4_CSI2_TX0_P: sheet HOST_CONNECTORS/AWR_4_CSI2_TX0_P, sheet AWR_4/CSI2_TX0_P
AWR_4_CSI2_TX1_N: sheet HOST_CONNECTORS/AWR_4_CSI2_TX1_N, sheet AWR_4/CSI2_TX1_N
AWR_4_CSI2_TX1_P: sheet HOST_CONNECTORS/AWR_4_CSI2_TX1_P, sheet AWR_4/CSI2_TX1_P
AWR_4_CSI2_TX2_N: sheet HOST_CONNECTORS/AWR_4_CSI2_TX2_N, sheet AWR_4/CSI2_TX2_N
AWR_4_CSI2_TX2_P: sheet HOST_CONNECTORS/AWR_4_CSI2_TX2_P, sheet AWR_4/CSI2_TX2_P
AWR_4_CSI2_TX3_N: sheet HOST_CONNECTORS/AWR_4_CSI2_TX3_N, sheet AWR_4/CSI2_TX3_N
AWR_4_CSI2_TX3_P: sheet HOST_CONNECTORS/AWR_4_CSI2_TX3_P, sheet AWR_4/CSI2_TX3_P
AWR_4_DIG_SYNCIN: sheet DIG_SYNC_LO_20GHZ/AWR_4_DIG_SYNCIN, sheet AWR_4/DIG_SYNCIN, sheet AWR_4/DIG_SYNCIN
AWR_4_DIG_SYNCOUT: sheet HOST_CONNECTORS/AWR_4_DIG_SYNCOUT, sheet AWR_4/DIG_SYNCOUT
AWR_4_FMCW_CLKOUT: sheet SYSTEM_TEST_CONN_TERMINATION/AWR_4_FMCW_CLKOUT, sheet AWR_4/FMCW_CLKOUT
AWR_4_FMCW_SYNCOUT: sheet SYSTEM_TEST_CONN_TERMINATION/AWR_4_FMCW_SYNCOUT, sheet AWR_4/FMCW_SYNCOUT
AWR_4_GPIO_0: sheet HOST_CONNECTORS/AWR_4_GPIO_0, sheet AWR_4/GPIO_0
AWR_4_GPIO_1: sheet HOST_CONNECTORS/AWR_4_GPIO_1, sheet AWR_4/GPIO_1
AWR_4_GPIO_2: sheet HOST_CONNECTORS/AWR_4_GPIO_2, sheet AWR_4/GPIO_2
AWR_4_LVDS_FRCLK_N: sheet HOST_CONNECTORS/AWR_4_LVDS_FRCLK_N, sheet AWR_4/LVDS_FRCLK_N
AWR_4_LVDS_FRCLK_P: sheet HOST_CONNECTORS/AWR_4_LVDS_FRCLK_P, sheet AWR_4/LVDS_FRCLK_P
AWR_4_LVDS_VALID_N: sheet HOST_CONNECTORS/AWR_4_LVDS_VALID_N, sheet AWR_4/LVDS_VALID_N
AWR_4_LVDS_VALID_P: sheet HOST_CONNECTORS/AWR_4_LVDS_VALID_P, sheet AWR_4/LVDS_VALID_P
AWR_4_MSS_LOGGER: sheet HOST_CONNECTORS/AWR_4_MSS_LOGGER, sheet AWR_4/MSS_LOGGER
AWR_4_NERROR_IN: sheet AWR_4/NERROR_IN, sheet AWR_4/NERROR_IN
AWR_4_NERROR_OUT: sheet HOST_CONNECTORS/AWR_4_NERROR_OUT, sheet AWR_4/NERROR_OUT
AWR_4_NRST: sheet SYSTEM_POWER/AWR_4_NRST, sheet SYSTEM_LED_INDICATORS/AWR_4_NRST, sheet AWR_4/NRST
AWR_4_NRST_HOST: sheet SYSTEM_POWER/AWR_4_NRST_HOST, sheet HOST_CONNECTORS/AWR_4_NRST
AWR_4_OSC_CLKOUT: sheet SYSTEM_TEST_CONN_TERMINATION/AWR_4_OSC_CLKOUT, sheet AWR_4/OSC_CLKOUT
AWR_4_PMIC_CLKOUT: sheet HOST_CONNECTORS/AWR_4_PMIC_CLKOUT, sheet AWR_4/PMIC_CLKOUT
AWR_4_SCL: sheet HOST_CONNECTORS/AWR_4_SCL, sheet AWR_4/SCL, sheet AWR_4/SCL
AWR_4_SDA: sheet HOST_CONNECTORS/AWR_4_SDA, sheet AWR_4/SDA, sheet AWR_4/SDA
AWR_4_SPI_CLK1: sheet HOST_CONNECTORS/AWR_4_SPI_CLK1, sheet AWR_4/SPI_CLK1, sheet AWR_4/SPI_CLK1
AWR_4_SPI_CS1: sheet HOST_CONNECTORS/AWR_4_SPI_CS1, sheet AWR_4/SPI_CS1, sheet AWR_4/SPI_CS1
AWR_4_SPI_HOST_INTR1: sheet HOST_CONNECTORS/AWR_4_SPI_HOST_INTR1, sheet AWR_4/SPI_HOST_INTR1, sheet AWR_4/SPI_HOST_INTR1
AWR_4_SPI_MISO1: sheet HOST_CONNECTORS/AWR_4_SPI_MISO1, sheet AWR_4/SPI_MISO1, sheet AWR_4/SPI_MISO1
AWR_4_SPI_MOSI1: sheet HOST_CONNECTORS/AWR_4_SPI_MOSI1, sheet AWR_4/SPI_MOSI1, sheet AWR_4/SPI_MOSI1
AWR_4_TCK: sheet HOST_CONNECTORS/AWR_4_TCK, sheet AWR_4/TCK
AWR_4_TDI: sheet HOST_CONNECTORS/AWR_4_TDI, sheet AWR_4/TDI
AWR_4_TDO: sheet HOST_CONNECTORS/AWR_4_TDO, sheet AWR_4/TDO
AWR_4_TMS: sheet HOST_CONNECTORS/AWR_4_TMS, sheet AWR_4/TMS
AWR_4_UART_RX: sheet HOST_CONNECTORS/AWR_4_UART_RX, sheet AWR_4/UART_RX, sheet AWR_4/UART_RX
AWR_4_UART_TX: sheet HOST_CONNECTORS/AWR_4_UART_TX, sheet AWR_4/UART_TX, sheet AWR_4/UART_TX
AWR_4_WARM_RST: sheet HOST_CONNECTORS/AWR_4_WARM_RST, sheet AWR_4/WARM_RST, sheet AWR_4/WARM_RST
AWR_4_XTAL_CLKM: sheet 40MHZ_CLOCK/AWR_4_XTALM, sheet AWR_4/XTAL_CLKM
AWR_4_XTAL_CLKP: sheet 40MHZ_CLOCK/AWR_4_XTALP, sheet AWR_4/XTAL_CLKP
EXT_40MHZ_CLK_1V8: sheet 40MHZ_CLOCK/EXT_40MHZ_BUFF_1V8_PRI, sheet HOST_CONNECTORS/EXT_40MHZ_CLK_1V8
EXT_DIG_SYNC: sheet DIG_SYNC_LO_20GHZ/EXT_DIG_SYNC, sheet HOST_CONNECTORS/EXT_DIG_SYNC
NERROR_OUT: sheet SYSTEM_LED_INDICATORS/NERROR_OUT, sheet HOST_CONNECTORS/NERROR_OUT
PMIC1_SCL: sheet HOST_CONNECTORS/PMIC1_SCL, sheet SYSTEM_POWER/PMIC1_I2C.PMIC1_SCL
PMIC1_SDA: sheet HOST_CONNECTORS/PMIC1_SDA, sheet SYSTEM_POWER/PMIC1_I2C.PMIC1_SDA
PMIC2_TMPSNS_SCL: sheet SYSTEM_TEMP_SENSORS/PMIC2_TMPSNS_SCL, sheet HOST_CONNECTORS/PMIC2_TMPSNS_SCL, sheet SYSTEM_POWER/PMIC2_I2C.PMIC2_SCL
PMIC2_TMPSNS_SDA: sheet SYSTEM_TEMP_SENSORS/PMIC2_TMPSNS_SDA, sheet HOST_CONNECTORS/PMIC2_TMPSNS_SDA, sheet SYSTEM_POWER/PMIC2_I2C.PMIC2_SDA
PMIC_BUCK_EN: sheet SYSTEM_POWER/PMIC_BUCK_EN, sheet HOST_CONNECTORS/PMIC_BUCKEN
PMIC_NRST: sheet SYSTEM_POWER/PMIC_NRST, sheet HOST_CONNECTORS/PMIC_NRST
SYSTEM_PGOOD: sheet SYSTEM_POWER/SYSTEM_PGOOD, sheet HOST_CONNECTORS/SYSTEM_PGOOD
TMPSNS_ALERT: sheet SYSTEM_TEMP_SENSORS/TMPSNS_ALERT, sheet HOST_CONNECTORS/TMPSNS_ALERT

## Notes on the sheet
- Cascade Radar RF Board  - Top Level Schematic
- AWR_1 (Master)
- AWR_3 (Slave)
- System Power/Reset
- 40MHz Generation/Distribution
- Digital Sync and 20GHZ LO
- AWR_2 (Slave)
- AWR_4 (Slave)
- System LED Indicators
- System Temperature Sensors
- System Test Connectors And Termination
